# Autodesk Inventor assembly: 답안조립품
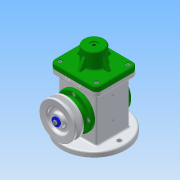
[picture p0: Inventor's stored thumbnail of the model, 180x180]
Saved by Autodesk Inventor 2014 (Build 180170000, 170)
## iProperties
Created: 2018-10
Part Number: 답안조립품
Document SubType Name: Assembly
Designer: Administrator
Author: Administrator
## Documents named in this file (18)
- C:\Users\Administrator\Desktop\481007V1007\답안조립품.iam
- C:\Users\Administrator\Desktop\481007V1007\본체.ipt
- C:\Users\Administrator\Desktop\481007V1007\덮개.ipt
- C:\Users\Administrator\Desktop\481007V1007\뒤커버.ipt
- C:\Users\Administrator\Desktop\481007V1007\앞커버.ipt
- C:\Users\Administrator\Desktop\481007V1007\베어링 17 x 40 x 12.ipt
- C:\Users\Administrator\Desktop\481007V1007\편심축.ipt
- C:\Users\Administrator\Desktop\481007V1007\링크.ipt
- C:\Users\Administrator\Desktop\481007V1007\슬라이더.ipt
- C:\Users\Administrator\Desktop\481007V1007\클레비스 핀 6 x 22.ipt
- 클레비스 핀 6 x 22.ipt
- C:\Users\Administrator\Desktop\481007V1007\오일 실 17 30 8.ipt
- C:\Users\Administrator\Desktop\481007V1007\볼트 M4 x 8.ipt
- C:\Users\Administrator\Desktop\481007V1007\E-링.ipt
- C:\Users\Administrator\Desktop\481007V1007\키 4 x 4 x 12.ipt
- C:\Users\Administrator\Desktop\481007V1007\V-벨트풀리.ipt
- C:\Users\Administrator\Desktop\481007V1007\와셔 4x16.ipt
- C:\Users\Administrator\Desktop\481007V1007\볼트 M4 x 10.ipt
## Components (2 placed, 2 different names)
1. E-링:1
2. V-벨트풀리:1 — 각도:2
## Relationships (1: Angle 1)
- 각도:2 [Angle]: V-벨트풀리:1
